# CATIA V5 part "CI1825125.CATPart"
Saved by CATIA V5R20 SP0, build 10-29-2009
Part number: CI1825125
Bounding box of the stored display mesh (mm): x -24 to 24, y -19.337 to 159.5, z -31.667 to 27.272
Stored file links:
  C:\Users\Raffaele\Desktop\3D X SITO CF\BOLEX\19-INCLINED ASSEMBLY REF_CI\CI1825125.CATPart

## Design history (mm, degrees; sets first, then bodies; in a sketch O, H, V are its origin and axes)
Set1
  DatumSurface1 to DatumSurface16 "MANIFOLD_SOLID_BREP #389"
  DatumSurface17 to DatumSurface39 "MANIFOLD_SOLID_BREP #1134"
Body1 (main body)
